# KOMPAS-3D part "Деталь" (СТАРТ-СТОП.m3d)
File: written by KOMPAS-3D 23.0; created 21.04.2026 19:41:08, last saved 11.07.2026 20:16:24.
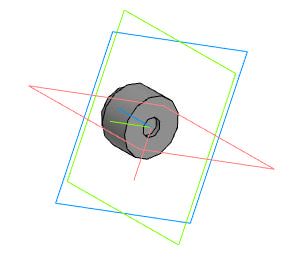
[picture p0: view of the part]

Document properties: Автор: D.LAB; Полное имя файла: C:\ЭЛЕКТРОНИКА\СХЕМЫ\Разное\ЦИФРОВОЙ ПРЕССОСТАТ ДЛЯ КОМПРЕССОРА\КОРПУС\1.0\СТАРТ-СТОП.m3d

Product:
- Part/product: Деталь
    Масса: 0.024784

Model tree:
1. Эскиз:4
2. Элемент выдавливания:4
     Расстояние 1 = 10
3. Эскиз:5  (with: Элемент выдавливания:4)
4. Элемент выдавливания:5
     Расстояние 1 = 3
5. Эскиз:6  (with: Элемент выдавливания:4)
6. Элемент выдавливания:6
     Расстояние 2 = 1.5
